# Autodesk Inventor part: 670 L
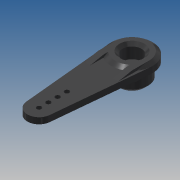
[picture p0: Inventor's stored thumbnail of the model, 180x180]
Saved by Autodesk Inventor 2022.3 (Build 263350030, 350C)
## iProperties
Created: 2021-08
Part Number: 670 L
Material: Nylon 6/6
Document SubType Name: Modeling
Designer: dotwibo2
Mass: 0.28903 g
Surface Area: 4.66998 cm^2
Volume: 0.255779 cm^3
Density: 1.13 g/cm^3
Appearance: Dark Gray
Description: SUPER STRENGTH LONG SERVO LARGE ARM
Vendor: DUBRO
UOFM: EACH
MAKE_OR_BUY: REF
PURCH_QTY: 0
BOM_MATL: -
Note: INCLUDED IN SET
Vendor Part No: 670 L
Alt_PN: DUBRO 670 L
Author: dotwibo2
Title: SUPER STRENGTH LONG SERVO LARGE ARM
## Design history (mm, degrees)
sketch "Sketch1"
  geometry: L1 (0, -7.52)-(0, 4.8) reference; L2 (1.65, -1.71)-(1.65, -2.76); L3 (1.65, -2.76)-(2.925, -2.76); L4 (2.925, -2.76)-(2.925, -5.76); L5 (2.925, -5.76)-(4.25, -5.76); L6 (5.5, -4.51)-(5.5, 0); L7 (5.5, 0)-(7.055, 0); L8 (7.055, 0)-(7.055, 2.1); L9 (7.055, 2.1)-(5.8, 3.04); L10 (5.8, 3.04)-(3.25, 3.04); L11 (-1.411, 0)-(8.466, 0) reference; L12 (1.65, -1.71)-(3.25, -1.71); L13 (3.25, -1.71)-(3.25, 3.04); L14 (5.5, -4.51)-(4.25, -5.76); 1 further point
  constraints: 25 end point, 5 horizontal, 5 vertical, 1 collinear
  dimensions: "d1" = 5.85 diameter of L4 L1; "d2" = 3.3 diameter of L2 L1; "d3" = 8.8 distance between parallel lines of L5 L10; "d7" = 11 diameter of L6 L1; "d9" = 5.76 distance between parallel lines of L7 L5; "d10" = 14.11 diameter of L8 L1; "d20" = 3 distance between parallel lines of L5 L3; "d48" = 6.5 diameter of L13 L1; "d49" = 4.75 distance between parallel lines of L10 L12; "d52" = 2.1 distance of L7.end L8.end; "d53" = 45 deg angle of L6 L14; "d54" = 8.5 diameter of L5.end L1; "d60" = 11.6 diameter of L9.end L1; "d66" = 0.94 vertical distance of L8.end L9.end (derived)
revolve "Revolution1" sketch "Sketch1" stored, may be unused: angle "d11" = 90 deg
sketch "Sketch3"
  geometry: L1 (-7.022, 0.679)-(-3.981, 32.135); L2 (3.981, 32.135)-(7.022, 0.679); L3 (9.877, 0)-(-9.877, 0) reference; L4 (0, -14.346)-(0, 36.691) reference; C1 r 7.055 at (0, 0) reference; A1 r 4 centre (0, 31.75) between (3.981, 32.135) and (-3.981, 32.135); A2 r 7.055 centre (0, 0) between (7.022, 0.679) and (-7.022, 0.679); 5 further points
  constraints: 4 end point, 4 point on circle, 3 point on line, 3 tangent, 2 centre point, 2 coincident, 1 concentric, 1 other
  dimensions: "d21" = 31.75 distance from line of L3 A1.centre; "d22" = 8 diameter of A1; "d23" = 9.525 distance of point (0, 22.225) A1.centre; "d29" = 3.175 distance of point (0, 31.75) point (0, 28.575); "d30" = 3.175 distance of point (0, 25.4) point (0, 28.575) (= d29)
extrude "Extrusion2" join sketch "Sketch3" distance "d27" = 2.1; taper "d28" = 0 deg
hole "Hole1" sketch "Sketch3" diameter "d31" = 1.5875; stored, may be unused: countersink angle "d35" = 90 deg, drill point angle "d37" = 118 deg; dims "d32" = 4, "d33" = 4, "d34" = 2, "d36" = 5
workplane "Work Plane1"
sketch "Sketch5"
  geometry: L1 (-5.265, 0)-(7.055, 0) reference; L2 (2.255, 0.679)-(2.255, -7.055) reference; L3 (2.255, 8.5)-(2.255, 0); L4 (2.255, 0)-(0.945, 0); L5 (0.945, 0)-(0.945, 4); L6 (0.945, 4)-(2.255, 8.5); L7 (5.295, 5.8)-(5.295, -5.8) reference; 1 further point
  constraints: 8 end point, 2 collinear, 2 vertical, 1 horizontal
  dimensions: "d55" = 4 distance of L4.end L5.end; "d56" = 8.5 distance from line of L1 L3.start; "d57" = 4.35 distance between parallel lines of L5 L7
extrude "Extrusion4" join sketch "Sketch5" distance "d58" = 1.72; taper "d59" = 0 deg
workplane "Work Plane2"
sketch "Sketch6"
  geometry: L1 (2.1, 32.135)-(2.1, 0.679) reference; L2 (-0.608, 0)-(3.648, 0) reference; L3 (2.1, 10.55)-(2.1, 0); L4 (2.1, 0)-(3.04, 0); L5 (3.04, 0)-(3.04, 5.8); L6 (3.04, 5.8)-(2.1, 10.55); L7 (3.04, 5.8)-(3.04, -5.8) reference; 1 further point
  constraints: 9 end point, 3 collinear, 2 vertical, 1 horizontal
  dimensions: "d62" = 5.8 distance from line of L2 L5.end; "d63" = 4.75 vertical distance of L5.end L3.start
extrude "Extrusion5" join sketch "Sketch6" distance "d64" = 2; taper "d65" = 0 deg
mirror "Mirror1"
chamfer "Chamfer1" distance "d67" = 1; stored, may be unused: second distance "d68" = 2, angle "d69" = 45 deg
body "Solid1"
other parameters: "d61" = 5.8 (= 0.5 x d60)
